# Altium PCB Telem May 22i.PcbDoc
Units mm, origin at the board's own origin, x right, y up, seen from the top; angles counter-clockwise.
Board outline 60 x 60 mm, 2 copper layers (Top Layer, Bottom Layer); 39 components, 34 nets, 219 pads, 46 vias.
Unrouted connection lines stored in the file: 1.
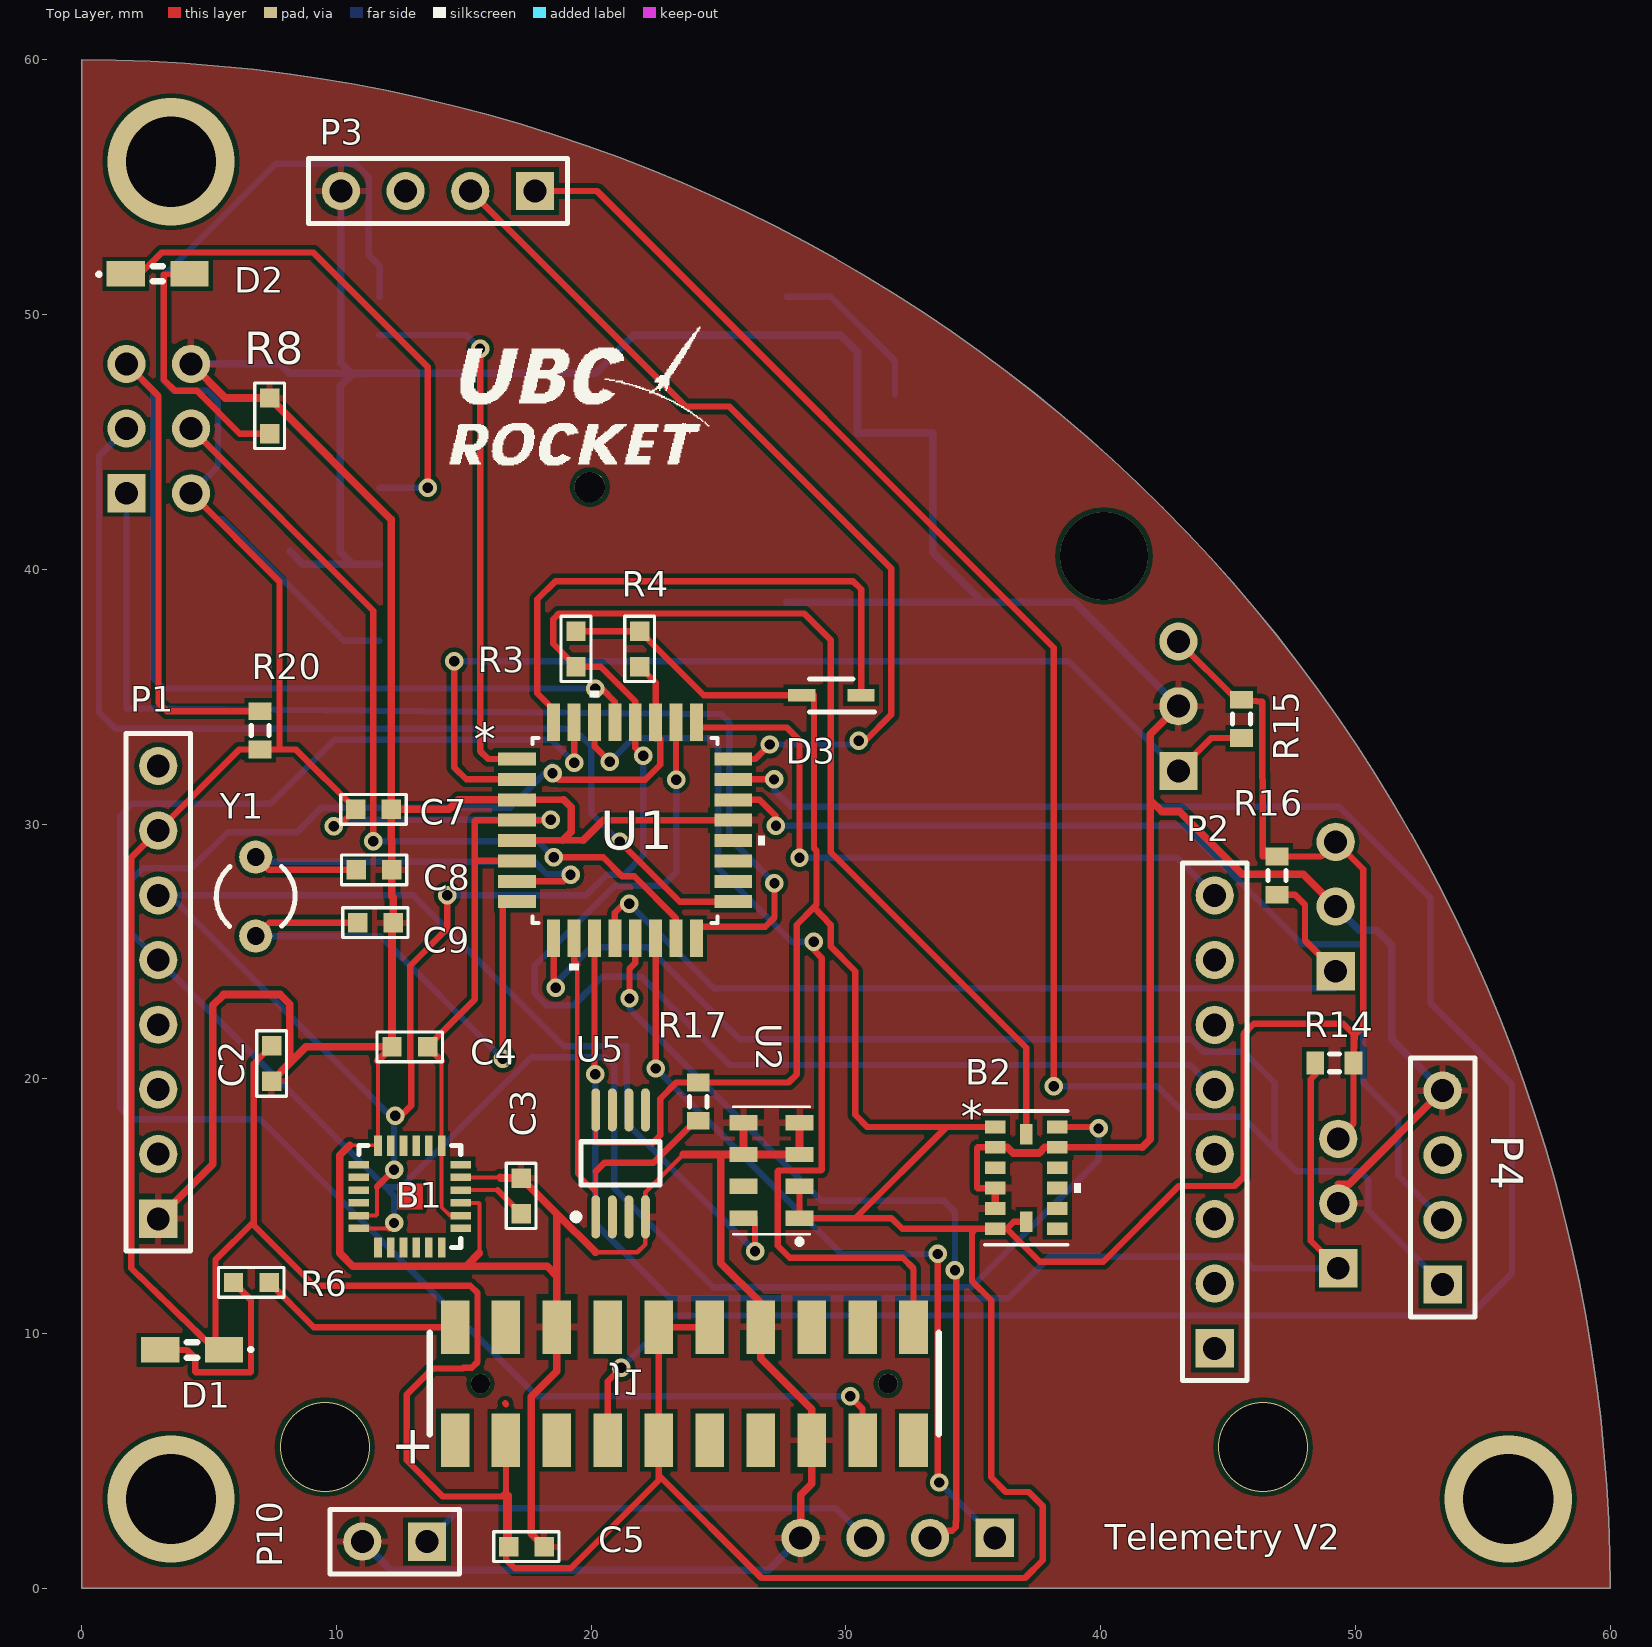
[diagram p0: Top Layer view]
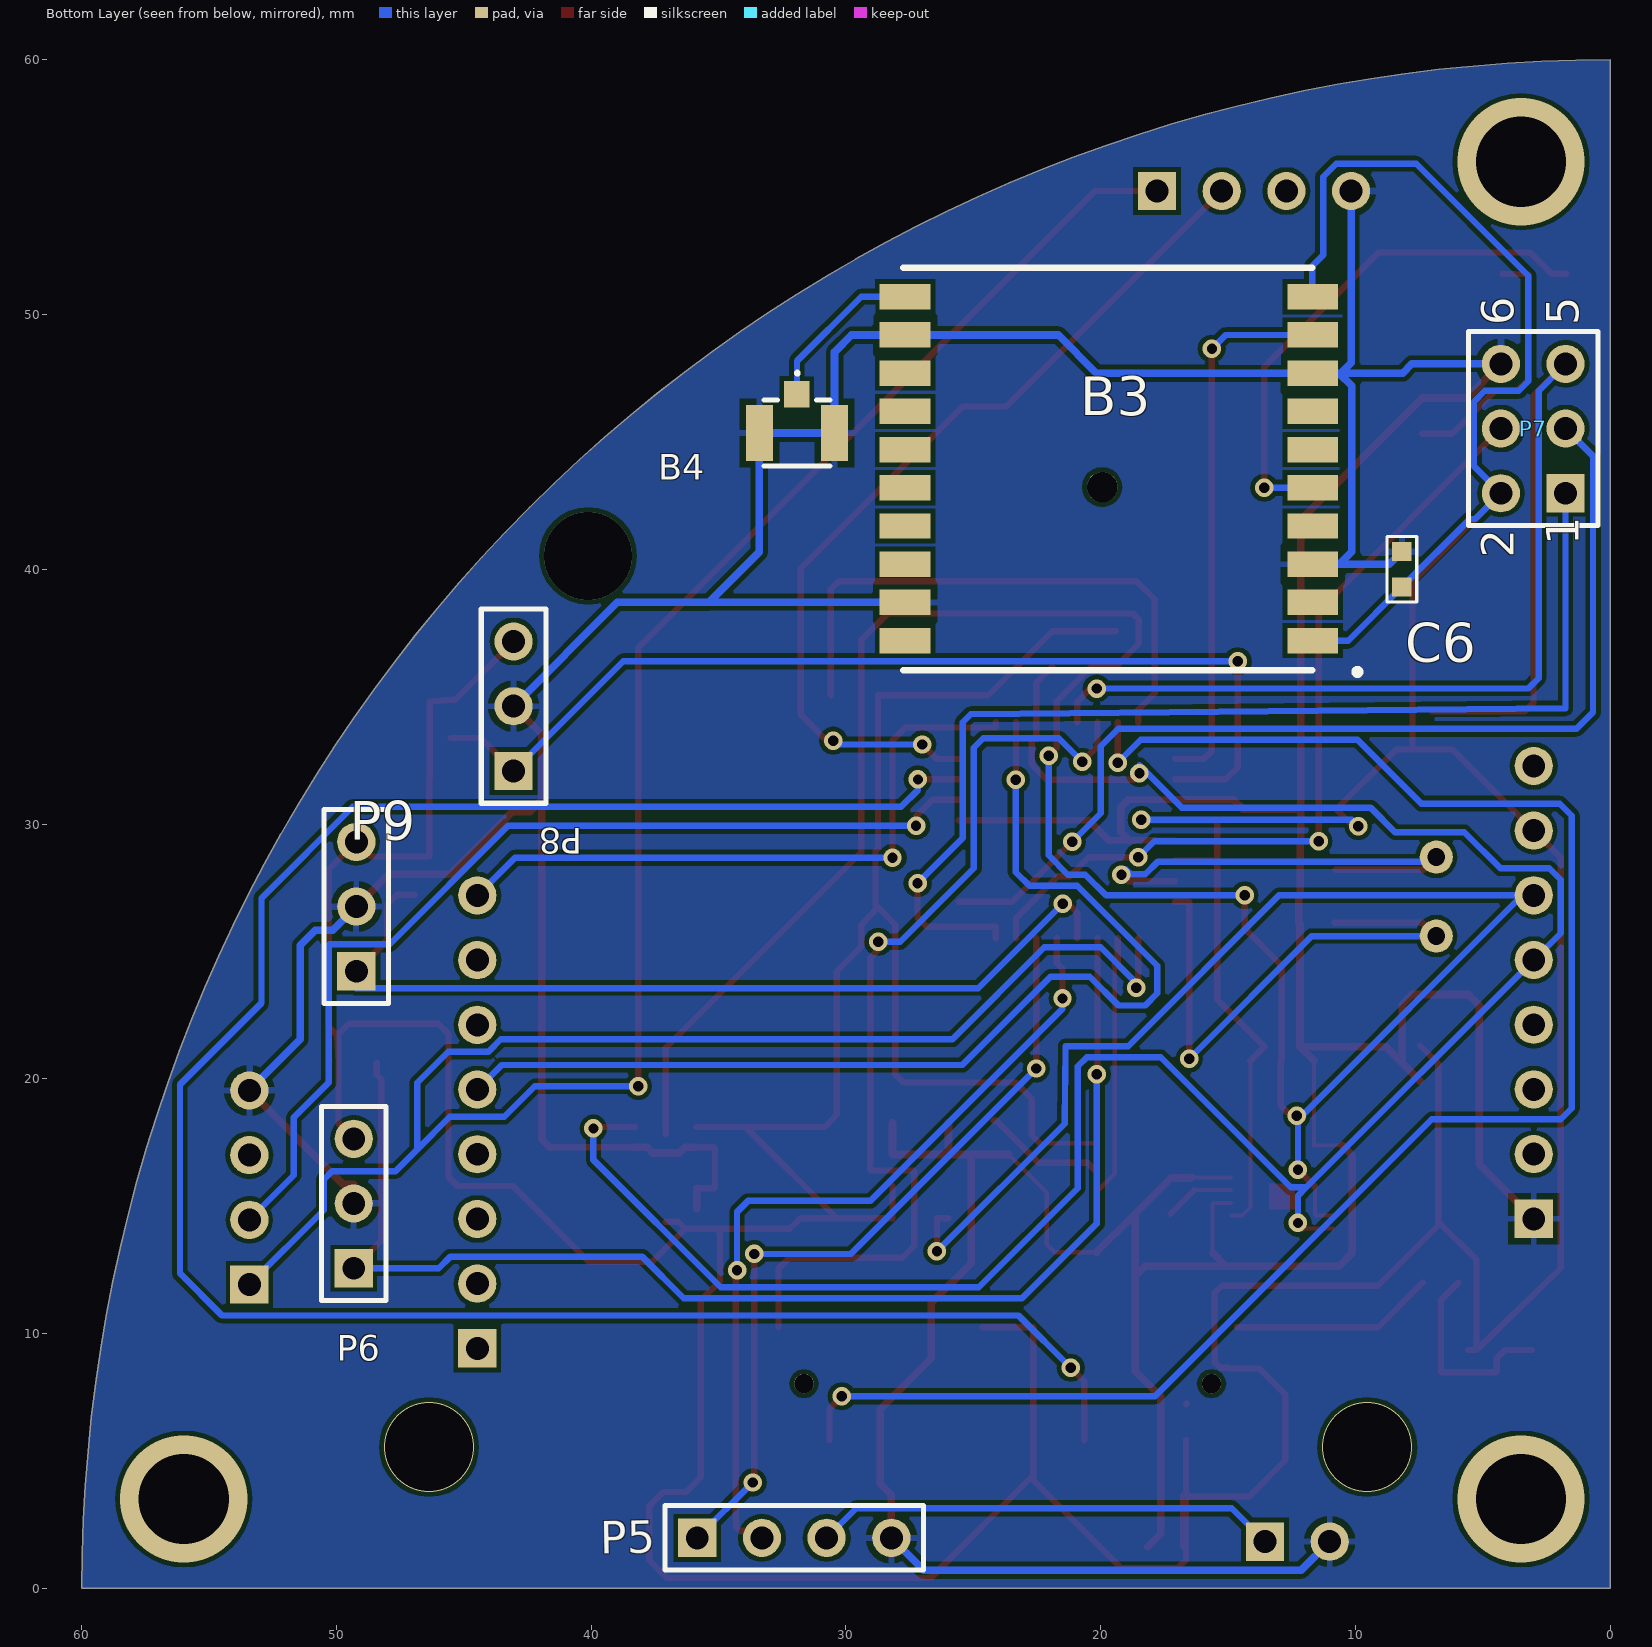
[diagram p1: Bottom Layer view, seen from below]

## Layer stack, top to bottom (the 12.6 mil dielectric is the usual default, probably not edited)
Top Solder: solder mask 0.0102, Solder Resist, Dk 3.5
Top Layer: signal copper 0.0356
Dielectric 1: dielectric 0.32, FR-4, Dk 4.8
Bottom Layer: signal copper 0.0356
Bottom Solder: solder mask 0.0102, Solder Resist, Dk 3.5

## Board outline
0,60 cw(c0,0) 60,0 0,0

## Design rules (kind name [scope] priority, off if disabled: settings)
Clearance [All] p1: gap=0.18 ignorepadtopadclearanceinfootprint=FALSE except(0: Arc-Hole Track-Hole SMDPad-Hole THPad-Hole Via-Hole Fill-Hole Poly-Hole Region-Hole Text-Hole)
Clearance Clearance_PWR [(InNet('ACT 12V') OR InNet('GND'))] p2: gap=0.25 ignorepadtopadclearanceinfootprint=FALSE except(0: Arc-Hole Track-Hole SMDPad-Hole THPad-Hole Via-Hole Fill-Hole Poly-Hole Region-Hole Text-Hole)
ComponentClearance [All] p1: gap=0.25 collisioncheckmode=3 verticalgap=0.25 showdistances=FALSE
Height [All] p1: minheight=0 maxheight=30 prefheight=12.7
HoleSize HoleSize_1 [IsVia] p1: absolutevalues=TRUE maxlimit=0.254 minlimit=0.025 maxpercent=80.000 minpercent=20.000
HoleSize [All] p2: absolutevalues=TRUE maxlimit=5 minlimit=0.025 maxpercent=80.000 minpercent=20.000
PlaneClearance [All] p1: clearance=1
PlaneConnect [All] p1: planeconnectstyle=Relief reliefexpansion=0.5 reliefentries=4 reliefconductorwidth=0.25 reliefairgap=0.25
PolygonConnect [All] p1: connectstyle=Relief reliefconductorwidth=0.25 reliefentries=4 polygonreliefangle="90 Angle" airgapwidth=0.25
RoutingCorners [All] p1: cornerstyle=45-Degree minsetback=0.25 maxsetback=0.25
RoutingVias [All] p1: holewidth=0.406 width=0.725 viastyle="Through Hole" minholewidth=0.406 minwidth=0.725 maxholewidth=0.406 maxwidth=0.725
SMDNeckDown [All] p1: percent=50.000
SilkToSilkClearance [All] p1: silktosilkclearance=0
SolderMaskExpansion [All] p1: expansion=0.1
Width Width_PWR [(InNet('ACT 12V') OR InNet('GND'))] p1: maxlimit=0.4 minlimit=0.1 preferedwidth=0.3 minimp=50.000000 maximp=50.000000 favimp=50.000000
Width [All] p2: maxlimit=0.25 minlimit=0.1 preferedwidth=0.25 minimp=50.000000 maximp=50.000000 favimp=50.000000
23 further rules are at their usual default settings.

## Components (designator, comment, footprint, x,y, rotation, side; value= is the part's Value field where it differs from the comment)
B1 "-Gyro-ITG-3400" QFN-24 12.875,15.375 r90 top
B2 "-Accelerometer-ADXL345" LGA_CC-14-1-L 37.075,16.107 r0 top
B3 "-GPS-FGPMMOPA6H" FGPMMOPA6H 27.745,36.028 r0 bottom
B4 "GPS antenna port-CONUFL001-SMD" CONUFL001-SMD 31.925,45.35 r0 bottom
C2 "0.1 uF" 0603C-GENERIC 7.45,19.9 r90 top
C3 "0.1 uF" 0603C-GENERIC 17.25,14.703 r90 top
C4 "10nF" 0603C-GENERIC 13.572,21.25 r180 top
C5 "0.1 uF" 0603C-GENERIC 16.753,1.625 r0 top
C6 "0.1 uF" 0603C-GENERIC 8.175,39.303 r90 bottom
C7 "0.1uF" 0603C-GENERIC 12.147,30.575 r180 top
C8 "22pF" 0603C-GENERIC 12.172,28.2 r180 top
C9 "22pF" 0603C-GENERIC 10.828,26.125 r0 top
D1 "LTST-S220KRKT" LTST-S220KFKT 4.325,9.35 r270 top
D2 "LTST-S220KRKT" LTST-S220KFKT 2.975,51.6 r90 top
D3 "1N4148WS-7-F" SOD2513X120N 29.425,35.05 r180 top
J1 "-Radio Socket- TLE-110-01-G-DV" TLE-110-01-G-DV 23.65,8.027 r180 top
P1 "Power Header" HDR1X8 3,14.5 r90 top
P2 "Data" HDR1X8 44.475,9.415 r90 top
P3 "Camera 1" HDR1X4 17.79,54.85 r180 top
P4 "Camera 2" HDR1X4 53.425,11.92 r90 top
P5 "SatCom" HDR1X4 35.84,1.975 r180 bottom
P6 "Temp1" HDR1X3 49.325,12.56 r90 bottom
P7 "ICSP" HDR2X3 1.75,42.985 r90 bottom
P8 "Temp2" HDR1X3 43.05,32.085 r90 bottom
P9 "Temp3" HDR1X3 49.225,24.22 r90 bottom
P10 "Lipo Battery" HDR1X2 13.55,1.825 r180 top
R3 "4.7k" 0603R-TBD 19.4,37.572 r270 top
R4 "4.7k" 0603R-TBD 21.9,37.572 r270 top
R6 "470" 0603R-TBD 7.35,12 r180 top
R8 "1k" 0603R-TBD 7.375,46.725 r270 top
R14 "Res3" J1-0603 49.175,20.625 r180 top value=4.7K
R15 "Res3" J1-0603 45.525,34.125 r270 top value=4.7K
R16 "Res3" J1-0603 46.925,27.975 r270 top value=4.7K
R17 "Res3" J1-0603 24.2,19.1 r90 top value=4.7K
R20 "10k" J1-0603 7,33.675 r90 top value=1K
U1 "-Microcontroller-ATMEGA328P-AUR" 32A 21.325,29.75 r0 top value=Value
U2 "-Barometer-MS560702BA03-50" MS5607-02BA03 27.075,16.4 r180 top
U5 "DS18B20U+T&R" MAXM-U8+1_N 21.15,16.675 r90 top
Y1 "16mhz XTAL" R38 6.825,27.15 r180 top

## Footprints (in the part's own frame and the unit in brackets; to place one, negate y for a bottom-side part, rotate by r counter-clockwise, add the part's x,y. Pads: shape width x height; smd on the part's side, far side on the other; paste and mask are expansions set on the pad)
32A [mil]
  rect 58x20 smd: 1(-167,110.24) 2(-167,78.74) 3(-167,47.24) 4(-167,15.75) 5(-167,-15.75) 6(-167,-47.24) 7(-167,-78.74) 8(-167,-110.24) 17(167,-110.24) 18(167,-78.74) 19(167,-47.24) 20(167,-15.75) 21(167,15.75) 22(167,47.24) 23(167,78.74) 24(167,110.24)
  rect 20x58 smd: 9(-110.24,-167) 10(-78.74,-167) 11(-47.24,-167) 12(-15.75,-167) 13(15.75,-167) 14(47.24,-167) 15(78.74,-167) 16(110.24,-167) 25(110.24,167) 26(78.74,167) 27(47.24,167) 28(15.75,167) 29(-15.75,167) 30(-47.24,167) 31(-78.74,167) 32(-110.24,167)
  silkscreen extent -143,-216 216,216, body extent -182,-182 182,182, height 47
0603C-GENERIC [mil] "CAPACITOR 0603"
  rect 30x30 smd: 1(0,0) 2(55,0)
  silkscreen extent -23,-23 78,23, body extent -4,-15 59,15, height 19
0603R-TBD [mil] "RESISTOR 0603 VALUE TO BE DETERMINED"
  rect 30x30 smd: 1(0,0) 2(55,0)
  silkscreen extent -23,-23 78,23, body extent -4,-15 59,15, height 20
CONUFL001-SMD [mm]
  rect 1x1.05 smd: 1(0,-1.525)
  rect 1.05x2.2 smd: 2(-1.475,0) 3(1.475,0)
  silkscreen extent -1.3,-2.38 1.3,1.3
FGPMMOPA6H [mm]
  rect 2x1 smd: 1(-16.07,-1.172) 2(-16.07,-2.672) 3(-16.07,-4.172) 4(-16.07,-5.672) 5(-16.07,-7.172) 6(-16.07,-8.672) 7(-16.07,-10.172) 8(-16.07,-11.672) 9(-16.07,-13.172) 10(-16.07,-14.672) 11(-0.07,-14.672) 12(-0.07,-13.172) 13(-0.07,-11.672) 14(-0.07,-10.172) 15(-0.07,-8.672) 16(-0.07,-7.172) 17(-0.07,-5.672) 18(-0.07,-4.172) 19(-0.07,-2.672) 20(-0.07,-1.172)
  round 1.2 hole 1.2 unplated: 21(-7.8,-7.2)
  silkscreen extent -17.93,-15.81 0,0.16
HDR1X2 [mm] "Connector; Header; 2 Position"
  rect 1.5x1.5 hole 0.9: 1(0,0)
  round 1.5 hole 0.9: 2(2.54,0)
  silkscreen extent -1.27,-1.27 3.81,1.27
HDR1X3 [mm] "Connector; Header; 3 Position"
  rect 1.5x1.5 hole 0.9: 1(0,0)
  round 1.5 hole 0.9: 2(2.54,0) 3(5.08,0)
  silkscreen extent -1.27,-1.27 6.35,1.27
HDR1X4 [mm] "Connector; Header; 4 Position"
  rect 1.5x1.5 hole 0.9: 1(0,0)
  round 1.5 hole 0.9: 2(2.54,0) 3(5.08,0) 4(7.62,0)
  silkscreen extent -1.27,-1.27 8.89,1.27
HDR1X8 [mm] "Connector; Header; 8 Position"
  rect 1.5x1.5 hole 0.9: 1(0,0)
  round 1.5 hole 0.9: 2(2.54,0) 3(5.08,0) 4(7.62,0) 5(10.16,0) 6(12.7,0) 7(15.24,0) 8(17.78,0)
  silkscreen extent -1.27,-1.27 19.05,1.27
HDR2X3 [mm] "Connector; Header; 3x2 Position"
  rect 1.5x1.5 hole 0.9: 1(0,0)
  round 1.5 hole 0.9: 2(0,2.54) 3(2.54,0) 4(2.54,2.54) 5(5.08,0) 6(5.08,2.54)
  silkscreen extent -1.27,-1.27 6.35,3.81
J1-0603 [mm] "Chip Resistor, Body 1.6x0.8mm, IPC High Density"
  rect 0.7x0.9 smd: 1(-0.75,0) 2(0.75,0)
  silkscreen extent -0.2,-0.35 0.2,0.35, body extent -0.85,-0.48 0.85,0.48, height 0.9
LGA_CC-14-1-L [mm]
  rect 0.813x0.5 smd paste+0 mask+0: 1(-1.218,2) 2(-1.218,1.2) 3(-1.218,0.4) 4(-1.218,-0.4) 5(-1.218,-1.2) 6(-1.218,-2) 8(1.219,-2) 9(1.219,-1.2) 10(1.219,-0.4) 11(1.219,0.4) 12(1.219,1.2) 13(1.219,2)
  rect 0.5x0.813 smd paste+0 mask+0: 7(0,-1.719) 14(0,1.718)
  silkscreen extent -1.63,-2.63 2.13,2.63, body extent 0,0 0.25,0.25, height 0.25
LTST-S220KFKT [mm]
  rect 1x1.5 smd: 1(0,1.25) 2(0,-1.25)
  silkscreen extent -0.3,-0.2 0.3,2.32
MAXM-U8+1_N [mm] "SOP, 8-Leads, Body 3x3mm, Pitch 0.65mm, IPC Medium Density"
  oval 1.7x0.35 smd mask+0.05: 1(-2.1,0.975) 2(-2.1,0.325) 3(-2.1,-0.325) 4(-2.1,-0.975) 5(2.1,-0.975) 6(2.1,-0.325) 7(2.1,0.325) 8(2.1,0.975)
  silkscreen extent -2.22,-1.55 0.85,1.87, body extent -1.55,-1.55 1.55,1.55, height 1.1
MS5607-02BA03 [mm]
  rect 1.1x0.6 smd: 1(-1.1,1.875) 2(-1.1,0.625) 3(-1.1,-0.625) 4(-1.1,-1.875) 5(1.1,-1.875) 6(1.1,-0.625) 7(1.1,0.625) 8(1.1,1.875)
  silkscreen extent -1.5,-2.5 1.5,2.9
QFN-24 [mm]
  rect 0.8x0.3 smd mask+0.05: 1(-2,1.25) 2(-2,0.75) 3(-2,0.25) 4(-2,-0.25) 5(-2,-0.75) 6(-2,-1.25) 13(2,-1.25) 14(2,-0.75) 15(2,-0.25) 16(2,0.25) 17(2,0.75) 18(2,1.25)
  rect 0.3x0.8 smd mask+0.05: 7(-1.25,-2) 8(-0.75,-2) 9(-0.25,-2) 10(0.25,-2) 11(0.75,-2) 12(1.25,-2) 19(1.25,2) 20(0.75,2) 21(0.25,2) 22(-0.25,2) 23(-0.75,2) 24(-1.25,2)
  Top Layer region: -0.501,0.5 0.5,0.5 0.5,-0.501 -0.501,-0.501
  silkscreen extent -2,-2 2,2
R38 [mm] "Crystal, Thru-Hole; 2 Leads; Body 3.1 x 8.2 mm (Dia.xH)"
  round 1.3 hole 0.7: 1(0,1.55) 2(0,-1.55)
  silkscreen extent -1.55,-1.19 1.55,1.17
SOD2513X120N [mm]
  rect 1.075x0.5 smd: 1(-1.162,0) 2(1.162,0)
  silkscreen extent -1.7,-0.65 0.85,0.65
TLE-110-01-G-DV [mm]
  rect 1.12x2.105 smd: 1(-9,2.222) 2(-9,-2.223) 3(-7,2.222) 4(-7,-2.223) 5(-5,2.222) 6(-5,-2.223) 7(-3,2.222) 8(-3,-2.223) 9(-1,2.222) 10(-1,-2.223) 11(1,2.222) 12(1,-2.223) 13(3,2.222) 14(3,-2.223) 15(5,2.222) 16(5,-2.223) 17(7,2.222) 18(7,-2.223) 19(9,2.222) 20(9,-2.223)
  round 0.76 hole 0.76 unplated: 21(-8,0) 22(8,0)
  silkscreen extent -10,-1.99 10,1.99

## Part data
B1: library part ITG-3400, "3-axis gyroscope, I2C at 400kHz or SPI at 1MHz, QFN-24", Manufacturer_Name=INVENSENSE
B2: library part ADXL345, "3-Axis Accelerometer IC", Manufacturer_Name="Analog Devices"
B3: library part FGPMMOPA6H, "GPS Standalone Module, 20-pin", Manufacturer_Name="GlobalTop Technology Inc."
B4: library part CONUFL001-SMD, "RF Connectors / Coaxial Connectors U.FL Straight Surface Mount Jack", Manufacturer_Name="Linx Technologies"
C2 C3 C4 C5 C6 C7 C8 C9: library part 0603C-1NF-50V-X7R, "CAPACITOR 0603 CERAMIC"
D1 D2: "Lite-On LTST-S220KRKT Red LED, 631 nm, 2012 (0805) Side View, Rectangle Lens SMD Package", Manufacturer_Name=Lite-On, RS Part Number=1689786
D3: "Diode Switching 150mA 75V 200mW SOD323 Diodes Inc 1N4148WS-7-F Switching Diode, 150mA 75V, 2-Pin SOD-323", Manufacturer_Name="Diodes Inc.", RS Part Number=9228070
J1: library part TLE-110-01-G-DV, "Receptacle 2mm SMT 10+10way Samtec TLE Series 2mm Pitch 20 Way 2 Row Straight PCB Socket, Surface Mount, Solder Termination", Manufacturer_Name=SAMTEC, RS Part Number=7656105
P1 P2: library part "Header 8", "Header, 8-Pin"
P3 P4 P5: library part "Header 4", "Header, 4-Pin"
P6 P8 P9: library part "Header 3", "Header, 3-Pin"
P7: library part "Header 3X2", "Header, 3-Pin, Dual row"
P10: library part "Header 2", "Header, 2-Pin"
R3 R4 R6 R8: library part 0603R-TBD, "RESISTOR 0603 VALUE TO BE DETERMINED"
R14 R15 R16 R17: "Resistor"
R20: library part Res3, "Resistor"
U1: library part ATMEGA328P-AUR, "Imported"
U2: library part MS560702BA03-50, "MS5607-02BA03 Series 3 V 1 to 120 kPa Absolute Barometric Pressure Sensor", Package="SMD-8 TE Connectivity"
U5: "High-Precision 1-Wire Digital Thermometer, -55 to 125 degC, 8-Pin SOP (U8+1), Pb-Free, Tape and Reel", Generic Part Number=DS18B20, Supplier Part Number 1=DS18B20U+T&RTR-ND, Temp. Thresh.="Programmable (NV)"
Y1: library part XTAL, "Crystal Oscillator"

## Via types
v1: diameter 0.725, hole 0.406, Top Layer to Bottom Layer, 40 vias
v2: diameter 5, hole 3.54, Top Layer to Bottom Layer, 3 vias
v3: diameter 3.54, hole 3.45, Top Layer to Bottom Layer, 2 vias
v4: diameter 3.45, hole 3.45, Top Layer to Bottom Layer, 1 vias

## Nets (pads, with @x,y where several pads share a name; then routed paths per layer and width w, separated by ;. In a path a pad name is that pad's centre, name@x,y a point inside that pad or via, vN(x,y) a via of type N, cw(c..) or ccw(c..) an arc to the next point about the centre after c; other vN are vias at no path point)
5V: P1.8
+3.3V: B1.8 B1.13 B2.1 B2.6 B2.7 B3.1 B3.10 C2.2 C4.1 C5.1 C6.1 C7.2 D1.1 D3.2 J1.10 J1.11 J1.12 J1.17 P1.7 P6.3 P7.2 P8.3 P9.3 R3.1 R4.1 R14.1 R15.1 R16.1 R17.2 R20.1 U1.4 U1.6 U2.1 U2.2 U5.8 | length 316.6
  Top Layer w0.15: 14.125,20.697 B1.13 14.125,14.953 14.453,14.625 B1.8
  Top Layer w0.175: U5.8 20.175,17.488 20.2,17.462 22.39,17.462
  Top Layer w0.25: P7.2 7.76,39.515 7.76,32.95 7.734,32.925 ; D1.1 D1.1@5.245,9.35 ; C2.2 6.744,20.591 6.744,14.389 ; v1(9.893,29.908) 10.083,29.908 C7.2 8.4,32.925 7.734,32.925 ; 14.125,20.697 C4.1 15.43,23.108 15.43,28.55 ; 16.625,7.252 16.65,7.226 ; J1.17 16.65,3.748 ; C5.1 16.753,3.645 16.65,3.748 ; U1.6 15.43,28.55 ; v1(18.402,30.162) 18.39,30.15 U1.4 15.456,30.15 15.43,30.125 15.43,28.55 ; R3.1 R4.1 24.422,35.05 D3.2 28.745,35.05 28.745,29.049 28.843,28.951 28.843,26.825 28.745,26.728 ; 22.39,17.462 22.708,17.78 22.708,19.215 23.343,19.85 R17.2 27.742,19.85 28.06,20.168 28.06,26.042 28.745,26.728 ; J1.10 J1.12 J1.11 22.65,4.432 ; U2.2 U2.1 30.366,14.525 ; B2.1 33.947,18.107 ; B2.7 36.591,14.388 36.309,14.107 ; P8.3 45.34,34.875 R15.1 46.342,34.799 46.368,28.725 R16.1 48.65,28.725 P9.3 50.305,28.22 50.305,22.034 49.975,21.705 ; P6.3 49.925,18.24 R14.1 ; D1.1@5.245,9.35 5.245,12.89 6.744,14.389 ; D1.1@5.245,9.35 1.943,12.56 1.943,28.683 P1.7 6.185,32.925 R20.1 7.734,32.925 ; 6.744,14.389 6.744,14.249 9.118,11.875 15.252,11.875 15.532,11.595 15.532,8.877 15.303,8.649 14.973,8.649 14.948,8.623 13.773,8.623 12.75,7.6 12.75,5.025 14.175,3.6 16.502,3.6 16.65,3.748 ; 16.65,3.748 16.65,1.117 16.993,0.775 19.196,0.775 22.65,4.229 22.65,4.432 ; 22.65,4.432 26.682,0.4 37.025,0.4 37.725,1.1 37.725,3.225 37.175,3.775 36.275,3.775 35.7,4.35 35.7,11.297 34.945,12.052 34.945,13.961 35.09,14.107 ; 28.745,26.728 29.395,26.042 29.395,25.19 30.366,24.219 30.366,18.58 30.839,18.107 33.947,18.107 ; 30.366,14.525 31.788,14.525 32.206,14.107 35.09,14.107 ; 30.366,14.525 33.947,18.107 ; 35.09,14.107 B2.6 36.309,14.107 ; 36.309,14.107 37.602,12.814 40.094,12.814 43.066,15.786 45.25,15.786 45.606,16.142 45.606,21.755 46.012,22.161 49.519,22.161 49.975,21.705 ; R14.1 49.975,21.705 ; R14.1 49.925,21.655 49.975,21.705
  Bottom Layer w0.25: v1(9.893,29.908) 10.147,30.162 v1(18.402,30.162) ; B3.1 10.278,37.2 C6.1 5.505,41.973 5.302,41.973 P7.2 5.347,44.042 5.347,46.584 4.928,47.003 3.594,47.003 3.213,47.384 3.213,51.524 7.607,55.918 10.757,55.918 11.265,55.41 11.265,52.337 11.697,51.905 11.697,50.7 B3.10
+5V: P5.3 P10.1 | length 18.2
  Bottom Layer w0.25: P10.1 14.862,3.137 29.598,3.137 P5.3
Ambient: R17.1 U1.10 U5.1 | length 16.9
  Top Layer w0.175: 19.451,24.481 19.451,16.27 20.175,15.546 ; U5.1 20.175,15.546 ; 20.175,16.358 20.175,15.546
  Top Layer w0.25: U1.10 19.325,24.607 19.451,24.481 ; 20.175,16.358 20.518,16.7 22.442,16.7 24.092,18.35 R17.1
GND: B1.9 B1.11 B1.18 B2.2 B2.4 B2.5 B2.12 B3.3 B3.8 B3.12 B3.19 B4.2 B4.3 C2.1 C3.2 C4.2 C5.2 C6.2 C7.1 C8.1 C9.2 J1.5 J1.8 J1.16 P1.1 P3.4 P4.4 P5.4 P6.2 P7.6 P8.2 P9.2 P10.2 R8.1 U1.3 U1.5 U1.21 U2.3 U2.4 U2.5 U2.6 U5.4 | length 289.6
  Top Layer w0.15: 10.516,17.386 B1.18@11.625,17.386 ; B1.18 B1.18@11.625,17.386 ; 11.625,20.7 B1.18@11.625,17.386 ; B1.9 15.583,15.125 15.608,15.1 15.608,13.157 ; B1.11 16.419,16.125
  Top Layer w0.175: 20.168,13.183 21.808,13.183 22.125,13.5 U5.4 22.125,15.541 23.609,17.025
  Top Layer w0.25: B2.4 35.166,15.706 35.141,15.732 35.141,17.281 35.166,17.307 B2.2 ; B2.12 41.627,17.307
  Top Layer w0.254: U1.5 17.851,29.35 17.86,29.359 18.877,29.359 19.683,29.359 ; U1.3 18.91,30.95 ; 20.474,30.15 U1.21
  Top Layer w0.3: P1.1 5.143,16.643 5.143,22.885 5.563,23.304 7.785,23.304 8.166,22.923 8.166,20.616 ; P7.6 5.63,46.725 R8.1 12.147,41.953 C7.1 ; C2.1 8.166,20.616 ; 10.516,17.386 10.122,16.993 10.122,13.157 10.643,12.636 15.088,12.636 ; 11.625,20.7 C4.2 ; 15.608,13.157 15.088,12.636 ; 16.419,16.125 16.444,16.1 C3.2 18.65,14.7 ; U1.3 14.789,30.95 14.414,30.575 C7.1 ; C5.2 17.64,2.135 17.64,7.512 18.65,8.522 J1.16 18.65,12.249 ; 18.877,29.359 19.211,29.693 19.211,30.649 18.91,30.95 ; 19.683,29.359 20.474,30.15 ; 20.168,13.183 18.65,14.7 ; 23.609,17.025 25.108,17.025 ; U2.5 U2.6 ; U2.4 U2.3 U2.6 ; P5.4 28.22,3.67 28.65,4.1 J1.5 28.65,7.023 26.65,9.023 J1.8 26.65,11.196 25.082,12.763 25.082,17 25.108,17.025 ; B2.5 B2.4 ; B2.2 36.335,17.307 36.56,17.081 37.579,17.081 37.804,17.307 B2.12 ; 41.627,17.307 41.948,17.628 41.948,30.937 ; P8.2 41.948,33.523 41.948,30.937 ; P9.2 47.956,28.029 45.555,28.029 43.091,30.493 42.393,30.493 41.948,30.937 ; P6.2 49.325,15.862 49.747,15.862 P4.4 ; 8.166,20.616 8.8,21.25 C4.2 ; C7.1 12.147,29.4 12.172,29.375 C8.1 12.172,27.167 12.225,27.114 C9.2 12.175,26.075 C4.2 ; 15.088,12.636 18.263,12.636 18.65,12.249 ; 18.65,12.249 18.65,14.7 ; 25.108,17.025 U2.6
  Bottom Layer w0.3: P7.6 7.785,48.065 8.15,47.7 10.578,47.7 ; C6.2 8.675,40.2 10.643,40.2 ; P3.4 10.17,48.108 10.578,47.7 ; P10.2 12.137,0.698 26.943,0.698 P5.4 ; B3.3 10.643,40.2 ; B3.19 35.378,38.7 ; P8.2 38.975,38.7 35.378,38.7 ; P9.2 50.156,25.829 50.834,25.829 51.422,25.24 51.422,21.543 P4.4 ; 10.578,47.7 10.61,47.667 ; 10.61,47.667 10.643,47.7 B3.8 ; 10.61,47.667 10.147,47.205 10.147,40.695 10.643,40.2 ; 10.61,47.667 B3.8 ; B3.8 20.166,47.7 21.666,49.2 B3.12 29.781,49.2 30.45,48.531 B4.2 B4.3 33.4,40.678 35.378,38.7
NetB1_10: B1.10 C3.1 | length 2.8
  Top Layer w0.15: B1.10 16.328,15.625
  Top Layer w0.25: 16.328,15.625 C3.1
NetB1_23: B1.23 B2.14 P1.6 R3.2 U1.28 U2.8 | length 113.3
  Top Layer w0.15: B1.23 11.545,14.625 11.588,14.668 11.588,15.753
  Top Layer w0.25: 11.588,15.753 v1(12.255,16.421) ; v1@12.3,18.325 12.925,18.95 12.925,20.665 12.886,20.704 12.886,24.436 14.35,25.9 v1(14.35,27.2) ; v1(22.042,32.677) 21.725,32.995 U1.28 21.725,34.815 20.365,36.175 R3.2 18.5,37.075 18.5,38.033 18.732,38.265 28.359,38.265 29.4,37.224 29.4,28.892 37.075,21.218 B2.14 ; U2.8 26.429,14.525 v1(26.429,13.221)
  Bottom Layer w0.25: P1.6 P1.6@3.45,27.2 ; v1(12.255,16.421) 12.255,18.395 P1.6@3.45,27.2 ; v1(14.35,27.2) 19.79,27.2 20.604,28.014 21.288,28.014 22.042,28.769 v1(22.042,32.677) ; v1(26.429,13.221) 21.411,18.238 21.38,21.278 18.922,21.278 13,27.2 P1.6@3.45,27.2
  other v1: 12.3,18.55
NetB1_24: B1.24 B2.13 P1.5 R4.2 U1.27 | length 88.4
  Top Layer w0.15: B1.24 v1@12.042,14.125
  Top Layer w0.25: v1@12.042,14.125 v1(12.255,14.338) ; v1(18.478,31.991) 18.727,31.743 22.123,31.743 22.71,32.329 22.71,33.345 22.525,33.345 U1.27 22.525,35.55 R4.2 ; B2.13 39.856,18.107 v1(39.916,18.047)
  Bottom Layer w0.25: v1(12.255,14.338) 12.255,15.405 11.925,15.735 ; v1(18.478,31.991) 18.478,32.309 16.815,30.645 9.411,30.645 8.445,29.68 5.728,29.68 4.305,28.257 2.388,28.257 1.943,27.813 1.943,25.717 P1.5 11.925,15.735 ; v1(39.916,18.047) 39.916,16.81 34.912,11.806 24.795,11.806 20.904,15.697 20.904,20.485 20.541,20.848 17.647,20.848 12.535,15.735 11.925,15.735
NetB3_5: B3.5 D2.1 | length 20.7
  Top Layer w0.25: D2.1 2.299,51.6 3.137,52.438 9.08,52.438 13.576,47.942 v1(13.576,43.2)
  Bottom Layer w0.25: B3.5 v1(13.576,43.2)
NetB3_9: B3.9 U1.1 | length 21.6
  Top Layer w0.25: v1(15.634,48.654) 15.634,32.868 15.951,32.55 U1.1
  Bottom Layer w0.25: B3.9 15.087,49.2 v1(15.634,48.654)
NetB3_11: B3.11 B4.1 | length 6.6
  Bottom Layer w0.25: B3.11 29.4,50.7 31.925,48.175 B4.1
NetC8_2: C8.2 U1.7 Y1.2 | length 19.2
  Top Layer w0.25: Y1.2 7.325,28.2 C8.2 ; U1.7 18.923,27.75 v1(19.186,28.013)
  Bottom Layer w0.25: Y1.2 7,28.525 17.749,28.525 18.253,28.022 18.806,28.022 18.991,28.207 v1(19.186,28.013)
NetC9_1: C9.1 U1.8 Y1.1 | length 22.6
  Top Layer w0.25: Y1.1 7.35,26.125 C9.1 ; v1(16.523,20.79) 16.523,26.95 U1.8
  Bottom Layer w0.25: Y1.1 11.712,25.6 v1(16.523,20.79)
NetD1_2: D1.2 R6.2 | length 8
  Top Layer w0.25: D1.2 4.127,9.35 4.445,9.032 4.445,8.496 4.47,8.471 6.617,8.471 6.642,8.496 6.642,11.311 R6.2
NetD2_2: D2.2 R8.2 | length 10.2
  Top Layer w0.25: D2.2 3.213,51.575 3.213,47.447 3.658,47.003 4.523,47.003 6.198,45.328 R8.2
NetD3_1: D3.1 U1.32 | length 22.4
  Top Layer w0.25: U1.32 18.525,34.48 17.875,35.13 17.875,38.817 18.593,39.535 30.277,39.535 30.594,39.218 30.594,35.05 D3.1
NetJ1_2: J1.2 U1.30 | length 38
  Top Layer w0.25: U1.30 20.125,33.05 v1(20.726,32.448) ; v1(28.727,25.375) 28.727,25.057 29.045,24.74 29.045,16.421 29.019,16.396 27.343,16.396 27.318,16.37 27.318,13.437 27.788,12.967 32.233,12.967 32.65,12.549 J1.2
  Bottom Layer w0.25: v1(20.726,32.448) 21.641,33.363 24.613,33.363 24.981,32.995 24.981,28.266 27.872,25.375 v1(28.727,25.375)
NetJ1_3: J1.3 U1.31 | length 67.8
  Top Layer w0.25: v1(19.325,32.41) U1.31 ; v1(30.162,7.531) 30.65,7.043 J1.3
  Bottom Layer w0.25: v1(19.325,32.41) 18.423,33.312 9.919,33.312 7.404,30.797 1.981,30.797 1.511,30.328 1.511,18.834 1.943,18.402 6.998,18.402 17.869,7.531 v1(30.162,7.531)
NetJ1_13: J1.13 U1.23 | length 85.2
  Top Layer w0.25: J1.13 20.65,8.128 v1(21.171,8.649) ; U1.23 v1(27.175,31.75)
  Bottom Layer w0.25: v1(21.171,8.649) 23.228,10.706 54.496,10.706 56.147,12.357 56.147,19.774 52.946,22.974 52.946,27.089 49.365,30.67 27.838,30.67 27.175,31.334 v1(27.175,31.75)
NetJ1_20: J1.20 R6.1 | length 8
  Top Layer w0.25: R6.1 9.101,10.249 J1.20
NetP2_5: P2.5 U1.26 | length 43.2
  Top Layer w0.25: U1.26 23.325,31.742 v1(23.33,31.737)
  Bottom Layer w0.25: v1(23.33,31.737) 23.33,28.105 22.796,27.572 20.917,27.572 17.775,24.43 17.775,23.35 18.25,22.875 19.3,22.875 20.425,24 21.974,24 25.438,20.536 43.514,20.536 P2.5
NetP2_8: P2.8 U1.25 | length 26
  Top Layer w0.25: U1.25 24.125,33.789 27.673,33.789 28.175,33.287 v1(28.175,28.675)
  Bottom Layer w0.25: v1(28.175,28.675) 42.995,28.675 P2.8
NetP3_1: P3.1 P4.1 U1.9 | length 100
  Top Layer w0.25: P3.1 20.225,54.85 38.15,36.925 v1(38.15,19.7) ; U1.9 18.525,23.65 v1(18.6,23.575)
  Bottom Layer w0.25: v1(18.6,23.575) 18.6,23.756 20.002,25.159 22.21,25.159 25.819,21.55 43.548,21.55 44.038,21.06 45.615,21.06 46.838,19.837 46.838,17.221 ; v1(38.15,19.7) 42.225,19.7 43.421,18.504 45.555,18.504 46.838,17.221 ; P4.1 50.508,14.837 50.508,16.04 50.178,16.37 47.688,16.37 46.838,17.221
NetP3_2: P3.2 U1.24 | length 35.3
  Top Layer w0.25: P3.2 23.707,46.393 25.413,46.393 31.775,40.031 31.775,34.3 30.75,33.275 v1(30.5,33.275) ; U1.24 26.441,32.55 v1(27.013,33.122)
  Bottom Layer w0.25: v1(27.013,33.122) 30.347,33.122 v1(30.5,33.275)
NetP4_2: P4.2 U1.22 | length 39.4
  Top Layer w0.25: U1.22 26.606,30.95 27.25,30.306 v1(27.25,29.925)
  Bottom Layer w0.25: v1(27.25,29.925) 43.26,29.925 43.269,29.934 47.917,25.286 50.279,25.286 50.305,25.26 50.305,19.85 51.676,18.478 51.676,16.209 P4.2
NetP5_1: P5.1 U1.14 | length 31.3
  Top Layer w0.25: v1(22.525,20.401) U1.14 ; v1(33.597,13.119) 33.597,4.218 v1(33.668,4.147)
  Bottom Layer w0.25: v1(22.525,20.401) 29.807,13.119 v1(33.597,13.119) ; v1(33.668,4.147) P5.1
NetP5_2: P5.2 U1.13 | length 32.5
  Top Layer w0.25: v1(21.5,23.15) 21.5,24.319 21.725,24.544 U1.13 ; P5.2 33.575,2.25 34.175,2.25 34.31,2.385 34.31,2.603 34.335,2.629 34.335,12.426 v1(34.277,12.484)
  Bottom Layer w0.25: v1(21.5,23.15) 21.5,22.747 29.045,15.202 33.845,15.202 34.277,14.77 v1(34.277,12.484)
NetP6_1: P6.1 R14.2 U1.11 | length 51
  Top Layer w0.25: U1.11 20.125,20.21 v1(20.155,20.18) ; R14.2 48.425,20.155 48.247,19.977 48.247,13.638 P6.1
  Bottom Layer w0.25: v1(20.155,20.18) 20.155,14.313 23.091,11.376 36.37,11.376 38.011,13.017 45.529,13.017 45.987,12.56 P6.1
NetP7_1: P7.1 U1.16 | length 44.3
  Top Layer w0.25: U1.16 24.125,25.971 26.835,25.971 27.191,26.327 v1(27.191,27.673)
  Bottom Layer w0.25: P7.1 1.75,34.546 25.108,34.303 25.413,33.998 25.413,29.451 v1(27.191,27.673)
NetP7_3: P7.3 U1.17 | length 41.1
  Top Layer w0.25: v1(21.12,29.299) 23.469,26.95 U1.17
  Bottom Layer w0.25: P7.3 0.673,44.448 0.673,34.392 1.321,33.744 19.317,33.744 20.002,33.058 20.002,30.416 v1(21.12,29.299)
NetP7_4: P7.4 U1.15 | length 33.1
  Top Layer w0.25: P7.4 11.443,38.372 v1(11.443,29.324) ; v1(18.529,28.689) 20.467,28.689 21.205,27.951 21.68,27.951 23.325,26.306 U1.15
  Bottom Layer w0.25: v1(11.443,29.324) 17.894,29.324 v1(18.529,28.689)
NetP7_5: P7.5 R20.2 U1.29 | length 50
  Top Layer w0.25: P7.5 3.01,46.805 3.01,34.755 3.34,34.425 R20.2 ; v1(20.155,35.319) 20.409,35.319 20.925,34.802 U1.29
  Bottom Layer w0.25: P7.5 2.807,47.008 2.807,35.725 3.213,35.319 v1(20.155,35.319)
NetP8_1: P8.1 R15.2 U1.2 | length 40
  Top Layer w0.25: v1(14.618,36.385) 14.618,32.22 15.088,31.75 U1.2 ; P8.1 44.34,33.375 R15.2
  Bottom Layer w0.25: v1(14.618,36.385) 38.75,36.385 P8.1
NetP9_1: P9.1 R16.2 U1.12 | length 35.9
  Top Layer w0.25: U1.12 20.925,26.518 21.281,26.873 v1(21.488,26.873) ; R16.2 47.629,27.225 48.019,26.835 48.019,25.426 P9.1
  Bottom Layer w0.25: v1(21.488,26.873) 24.803,23.558 49.225,23.558 P9.1
pads on no net: B1.1 B1.2 B1.3 B1.4 B1.5 B1.6 B1.7 B1.12 B1.14 B1.15 B1.16 B1.17 B1.19 B1.20 B1.21 B1.22 B2.3 B2.8 B2.9 B2.10 B2.11 B3.2 B3.4 B3.6 B3.7 B3.13 B3.14 B3.15 B3.16 B3.17 B3.18 B3.20 B3.21 J1.1 J1.4 J1.6 J1.7 J1.9 J1.14 J1.15 J1.18 J1.19 J1.21 J1.22 P1.2 P1.3 P1.4 P2.1 P2.2 P2.3 P2.4 P2.6 P2.7 P3.3 P4.3 U1.18 U1.19 U1.20 U2.7 U5.2 U5.3 U5.5 U5.6 U5.7
copper on no net:
  other v2: 3.5,3.5 56,3.5 3.5,56
  other v3: 9.54,5.54 46.37,5.54
  other v4: 40.128,40.528

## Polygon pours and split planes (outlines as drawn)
GND on Bottom Layer "bottom" (solid, pour order 0): 0,60 cw(c0,0) 60,0 0,0
GND on Top Layer "Top Layer-No Net" (solid, pour order 1): 0,60 cw(c0,0) 60,0 0,0

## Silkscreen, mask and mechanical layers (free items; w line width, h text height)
Top Overlay:
  drawing of 13 lines, arcs and shapes, not listed
  text "+" at 12.125,4.875 h1.52
  text "Telemetry V2" at 40.15,1.5 h1
Mechanical 1:
  lines w0.254: 0,60 0,0 60,0 ; 0,60.185 cw(c0,0) 60.185,0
